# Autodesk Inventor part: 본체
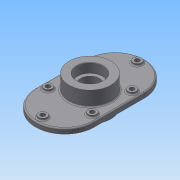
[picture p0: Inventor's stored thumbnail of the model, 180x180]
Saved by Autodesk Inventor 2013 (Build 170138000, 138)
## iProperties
Created: 2015-02
Part Number: 본체
Material: 일반
Document SubType Name: Modeling
Designer: ST4
Density: 1 g/cm^3
Author: ST4
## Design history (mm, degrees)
sketch "스케치1"
  geometry: L1 (70, 60)-(70, -60); L2 (-70, -60)-(-70, 60); A1 r 70 centre (0, 60) between (70, 60) and (-70, 60); A2 r 70 centre (0, -60) between (-70, -60) and (70, -60); 6 further points
  constraints: 5 point on circle, 4 end point, 3 vertical alignment, 2 centre point, 2 coincident, 2 horizontal alignment, 2 midpoint, 1 parallel
  dimensions: "d2" = 140 distance of L1.end L2.start; "d3" = 120 distance of L1.start L1.end; "d4" = 70 radius of A1; "d5" = 70 radius of A2
extrude "돌출1" new body sketch "스케치1" stored distance "d6" = 12; taper "d7" = 0 deg
sketch "스케치2"
  geometry: L1 (-70, 60)-(-70, -60) reference; L2 (70, -60)-(70, 60) reference; L3 (-53, 60)-(-53, -60); L4 (53, -60)-(53, 60); L5 (53, 37.5)-(53, -37.5); C1 r 10 at (0, 113); A1 r 70 centre (0, -60) between (-70, -60) and (70, -60) reference; A2 r 70 centre (0, 60) between (70, 60) and (-70, 60) reference; A3 r 53 centre (0, -60) between (-53, -60) and (53, -60); A4 r 53 centre (0, 60) between (53, 60) and (-53, 60); 3 further points
  constraints: 6 end point, 5 point on circle, 3 centre point, 1 coincident, 1 collinear, 1 horizontal alignment, 1 midpoint, 1 point on line, 1 vertical alignment, 3 other
  dimensions: "d8" = 17 distance between parallel lines of L2 L4; "d9" = 20 diameter of C1; "d21" = 75 distance of L5.end L5.start
extrude "돌출2" join sketch "스케치2" distance "d10" = 5; taper "d11" = 0 deg
hole "구멍1" diameter "d14" = 11; stored, may be unused: countersink angle "d18" = 90 deg, drill point angle "d20" = 118 deg; dims "d12" = 10, "d13" = 10, "d15" = 6, "d16" = 4, "d17" = 2, "d19" = 8
sketch "스케치3"
  geometry: L1 (70, -60)-(70, 60) reference; L2 (53, 47.5)-(53, -47.5); C1 r 10 at (53, 47.5); C2 r 10 at (53, -47.5); 2 further points
  constraints: 2 centre point, 2 coincident, 2 end point, 1 equal radius, 1 horizontal alignment, 1 midpoint, 1 parallel
  dimensions: "d22" = 95 distance of L2.end L2.start; "d23" = 53 horizontal distance of point (0, 0) L2.end; "d24" = 20 diameter of C1
extrude "돌출3" join sketch "스케치3" distance "d25" = 5; taper "d26" = 0 deg
hole "구멍2" diameter "d29" = 11; stored, may be unused: countersink angle "d33" = 90 deg, drill point angle "d35" = 118 deg; dims "d27" = 10, "d28" = 10, "d30" = 6, "d31" = 4, "d32" = 2, "d34" = 8
hole "구멍3" diameter "d38" = 11; stored, may be unused: countersink angle "d42" = 90 deg, drill point angle "d44" = 118 deg; dims "d36" = 10, "d37" = 10, "d39" = 6, "d40" = 4, "d41" = 2, "d43" = 8
sketch "스케치4"
  geometry: C1 r 50 at (0, 0); 1 further point
  constraints: 1 centre point, 1 coincident
  dimensions: "d45" = 100 diameter of C1
extrude "돌출4" join sketch "스케치4" distance "d47" = 35; taper "d48" = 0 deg
sketch "스케치5"
  geometry: C1 r 50 at (0, 0); 1 further point
  constraints: 1 centre point, 1 coincident
  dimensions: "d49" = 100 diameter of C1
extrude "돌출5" join sketch "스케치5" distance "d51" = 23; taper "d52" = 0 deg
hole "구멍4" diameter "d55" = 45; stored, may be unused: countersink angle "d59" = 90 deg, drill point angle "d61" = 0 deg; dims "d53" = 10, "d54" = 10, "d56" = 6, "d57" = 62, "d58" = 22, "d60" = 8
hole "구멍5" diameter "d64" = 62; stored, may be unused: countersink angle "d68" = 90 deg, drill point angle "d70" = 0 deg; dims "d62" = 10, "d63" = 10, "d65" = 6, "d66" = 62, "d67" = 22, "d69" = 22
sketch "스케치6"
  geometry: L1 (0, 0)-(-13.231, 0); C1 r 31 at (0, 0) reference; C2 r 50 at (0, 0) reference; 1 further point
  constraints: 2 end point, 1 horizontal
  dimensions: "d71" = 41 distance of point (-28.991, 28.991) C1.centre; "d72" = 45 deg dimension on C1.centre point (-28.991, 28.991) L1.end; "d73" = 13.23083 distance of L1.start L1.end
hole "구멍6" sketch "스케치6" at (-28.991, 28.991) diameter "d74" = 4.917; stored, may be unused: countersink angle "d78" = 90 deg, drill point angle "d80" = 118 deg; dims "d75" = 10, "d76" = 62, "d77" = 22, "d79" = 13
fillet "모깎기1" dims "d84" = 3
fillet "모깎기2" dims "d85" = 3
chamfer "모따기1" distance "d86" = 1; stored, may be unused: second distance "d87" = 2, angle "d88" = 45 deg
chamfer "모따기2" distance "d89" = 1; stored, may be unused: second distance "d90" = 2, angle "d91" = 45 deg
fillet "모깎기3" dims "d92" = 0.3
fillet "모깎기4" dims "d93" = 3
fillet "모깎기5" dims "d94" = 3
node "솔리드1"
mirror "대칭1"
mirror "대칭2"
pattern_circular "원형 패턴1" dims angle "d82" = 360 deg
